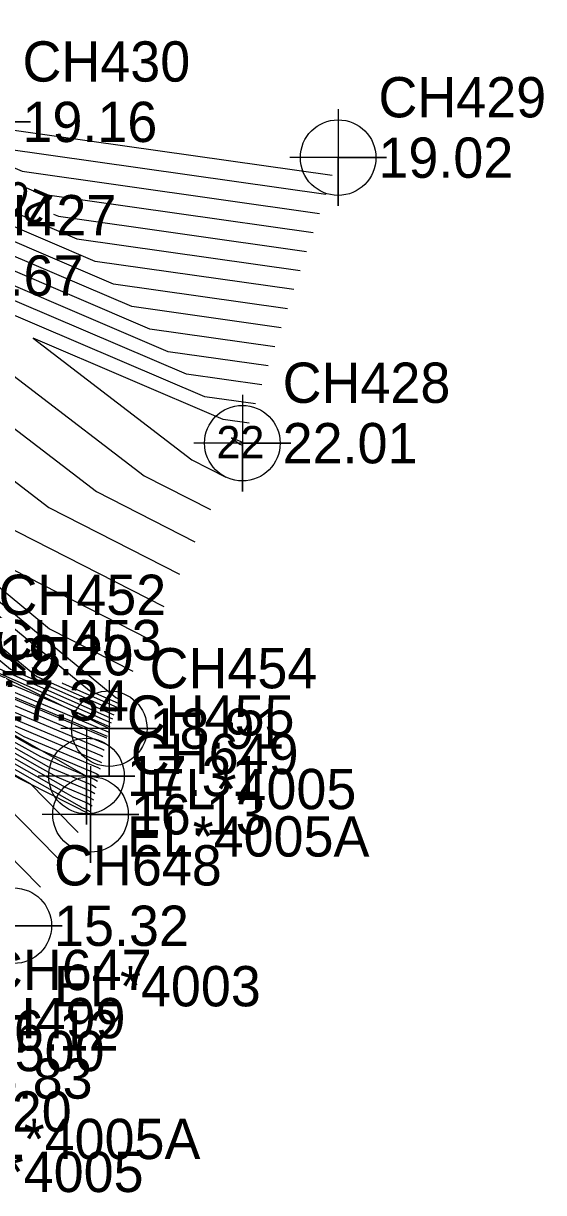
# Model space of a CAD drawing. Extents: x 2531902 to 2533249, y 715219 to 716099.
# Drawn here: x 2533024 to 2533056.3, y 715549.3 to 715621.9 of the extents above; entities that cross this region are included whole.
import ezdxf

# ---------------------------------------------------------------- set-up
doc = ezdxf.new("R2010")
doc.units = 0
for name, color, linetype in [('DTM Contours Major', 7, 'Continuous'), ('DTM Contours Major Text', 7, 'Continuous'), ('DTM Contours Minor', 7, 'Continuous'), ('Exist DTM Breakline', 7, 'Continuous'), ('Exist DTM Breakline Cogo Comment', 7, 'Continuous'), ('Exist DTM Breakline Cogo Elevation', 7, 'Continuous'), ('Exist DTM Breakline Cogo Number', 7, 'Continuous'), ('Exist DTM Breakline Cogo Point CELL', 7, 'Continuous'), ('Exist DTM Breakline Underwater', 7, 'Continuous'), ('Exist DTM Breakline Underwater Cogo Elevation', 7, 'Continuous'), ('Exist DTM Breakline Underwater Cogo Number', 7, 'Continuous'), ('Exist DTM Breakline Underwater Cogo Point CELL', 7, 'Continuous'), ('Exist DTM Drainline Cogo Comment', 7, 'Continuous'), ('Exist DTM Drainline Cogo Elevation', 7, 'Continuous'), ('Exist DTM Drainline Cogo Number', 7, 'Continuous'), ('Exist DTM Drainline Cogo Point CELL', 7, 'Continuous'), ('Exist DTM QL2 LIDAR Elevation Point', 7, 'Continuous'), ('Exist DTM Regular Point CELL', 7, 'Continuous'), ('Exist DTM Regular Point Cogo Elevation', 7, 'Continuous'), ('Exist DTM Regular Point Cogo Number', 7, 'Continuous'), ('Exist Hydro Stream or Body of Water', 7, 'Continuous'), ('Scratch_Level_2', 7, 'Continuous')]:
    doc.layers.add(name, color=color, linetype=linetype)

msp = doc.modelspace()

# ---------------------------------------------------------------- linework, layer by layer
at = {"layer": 'DTM Contours Major'}
for points in [[(2532946.87, 715617.429), (2532949.185, 715616.629), (2532951.913, 715615.738), (2532952.113, 715615.673), (2532964.207, 715610.955), (2532978.111, 715605.531), (2532979.345, 715604.806), (2532982.815, 715603.469), (2532989.141, 715601.029), (2532990.474, 715600.505), (2533006.727, 715590.482), (2533014.759, 715585.529), (2533016.174, 715584.657), (2533019.037, 715582.891), (2533020.493, 715582.065), (2533026.359, 715579.597), (2533029.394, 715578.257)], [(2533027.418, 715571.699), (2533027.176, 715571.946), (2533024.464, 715574.711), (2533004.98, 715585.771), (2533004.053, 715586.343), (2532998.79, 715589.588), (2532985.911, 715594.657), (2532977.232, 715595.627), (2532971.299, 715601.801), (2532961.938, 715607.296), (2532956.811, 715609.296), (2532955.068, 715609.865), (2532954.985, 715609.892), (2532953.857, 715610.261), (2532939.12, 715615.075)], [(2533025.904, 715610.066), (2533026.215, 715609.934), (2533041.601, 715607.751)], [(2533039.617, 715601.837), (2533031.881, 715602.934), (2533018.115, 715608.817), (2533015.15, 715607.045), (2533014.024, 715604.696)], [(2532980.883, 715601.698), (2532985.071, 715600.083), (2532987.721, 715599.04), (2532993.246, 715596.866), (2533011.19, 715585.8), (2533014.351, 715583.851), (2533020.078, 715580.601), (2533023.041, 715578.919), (2533028.859, 715576.471), (2533028.95, 715576.418)], [(2533014.217, 715601.218), (2533019.348, 715593.401), (2533022.641, 715590.878), (2533032.745, 715585.719)], [(2532977.433, 715600.777), (2532977.942, 715600.478), (2532978.745, 715600.007), (2532981.001, 715599.137), (2532981.993, 715598.747), (2532996.018, 715593.227), (2533007.622, 715586.072), (2533009.666, 715584.811), (2533024.201, 715576.56), (2533025.589, 715575.773), (2533028.313, 715574.627), (2533028.543, 715574.492)], [(2533037.633, 715595.922), (2533037.548, 715595.934), (2533036.934, 715596.197), (2533037.448, 715595.803), (2533037.558, 715595.747)], [(2533026.435, 715580.993), (2533026.495, 715580.944), (2533029.818, 715579.476)]]:
    msp.add_lwpolyline(points, dxfattribs=at)
at = {"layer": 'DTM Contours Minor'}
for points in [[(2532999.725, 715666.213), (2532993.26, 715656.52), (2532990, 715657.203), (2532984.051, 715655.949), (2532981.833, 715650), (2532981.031, 715641.031), (2532980.146, 715640.005), (2532980.058, 715630.034), (2532980.052, 715629.948), (2532982.278, 715610.95), (2532990.504, 715610.734), (2532998.305, 715604.477), (2533003.474, 715602.891), (2533010.173, 715601.89), (2533013.092, 715607.98), (2533019.576, 715611.855), (2533027.348, 715608.534), (2533041.204, 715606.568)], [(2532999.111, 715657.744), (2532992.201, 715647.385), (2532986.018, 715640.219), (2532985.959, 715633.551), (2532985.336, 715624.604), (2532986.72, 715612.801), (2532991.83, 715612.667), (2532996.677, 715608.78), (2533006.812, 715605.669), (2533010.47, 715605.123), (2533012.063, 715608.448), (2533020.306, 715613.374), (2533025.081, 715611.334), (2533041.997, 715608.934)], [(2532998.803, 715653.509), (2532993.605, 715645.716), (2532988.954, 715640.325), (2532988.909, 715635.309), (2532987.979, 715621.932), (2532988.94, 715613.726), (2532992.493, 715613.633), (2532995.863, 715610.931), (2533008.481, 715607.058), (2533010.618, 715606.739), (2533011.549, 715608.682), (2533020.671, 715614.134), (2533023.948, 715612.733), (2533042.394, 715610.117)], [(2532998.496, 715649.275), (2532995.01, 715644.048), (2532991.89, 715640.432), (2532991.86, 715637.067), (2532990.621, 715619.26), (2532991.161, 715614.652), (2532993.156, 715614.6), (2532995.049, 715613.082), (2533010.15, 715608.448), (2533010.766, 715608.356), (2533011.034, 715608.915), (2533021.036, 715614.893), (2533022.814, 715614.133), (2533042.791, 715611.3)], [(2532998.189, 715645.04), (2532996.414, 715642.379), (2532994.826, 715640.538), (2532994.81, 715638.826), (2532993.263, 715616.589), (2532993.382, 715615.578), (2532993.819, 715615.566), (2532994.235, 715615.233), (2532999.401, 715613.648), (2533018.93, 715614.175), (2533021.402, 715615.653), (2533021.681, 715615.533), (2533043.188, 715612.483)], [(2532960.276, 715619.792), (2532971.782, 715617.235), (2532979.897, 715609.186), (2532988.55, 715609.368), (2532989.991, 715608.846), (2532997.052, 715600.355), (2533004.549, 715595.73), (2533018.265, 715588.265), (2533019.992, 715587.199), (2533028.126, 715580.505), (2533029.903, 715579.72)], [(2532953.849, 715617.426), (2532972.271, 715610.766), (2532976.567, 715609.811), (2532979.597, 715606.806), (2532982.828, 715606.874), (2532989.957, 715604.29), (2532992.804, 715600.868), (2533011.106, 715589.575), (2533016.59, 715586.59), (2533019.985, 715584.495), (2533023.232, 715581.822), (2533029.648, 715578.988)], [(2532951.845, 715616.587), (2532976.27, 715607.757), (2532978.162, 715607.337), (2532979.497, 715606.013), (2532980.92, 715606.043), (2532989.946, 715602.772), (2532991.387, 715601.038), (2533013.292, 715587.523), (2533016.032, 715586.032), (2533019.983, 715583.593), (2533021.601, 715582.262), (2533029.564, 715578.745)], [(2532952.426, 715615.248), (2532971.074, 715607.973), (2532977.032, 715605.649), (2532979.285, 715604.326), (2532985.616, 715601.886), (2532988.327, 715600.84), (2532991.029, 715599.777), (2532997.994, 715595.482), (2533014.046, 715585.583), (2533016.873, 715583.84), (2533018.1, 715583.083), (2533021.003, 715581.435), (2533026.064, 715579.307), (2533029.296, 715577.947)], [(2532952.739, 715614.823), (2532975.954, 715605.766), (2532976.276, 715605.578), (2532979.225, 715603.846), (2532987.513, 715600.651), (2532991.158, 715599.216), (2532991.583, 715599.049), (2533013.332, 715585.638), (2533017.163, 715583.275), (2533017.603, 715583.025), (2533021.512, 715580.806), (2533029.187, 715577.578), (2533029.194, 715577.574)], [(2532953.053, 715614.397), (2532974.876, 715605.884), (2532976.484, 715604.94), (2532979.165, 715603.367), (2532986.699, 715600.462), (2532990.013, 715599.158), (2532992.138, 715598.321), (2533012.618, 715585.692), (2533016.226, 715583.467), (2533018.428, 715582.217), (2533022.022, 715580.177), (2533029.078, 715577.209), (2533029.113, 715577.189)], [(2532953.366, 715613.972), (2532973.798, 715606.002), (2532976.693, 715604.303), (2532979.105, 715602.887), (2532985.885, 715600.272), (2532988.867, 715599.099), (2532992.692, 715597.594), (2533011.904, 715585.746), (2533015.289, 715583.659), (2533019.253, 715581.409), (2533022.532, 715579.548), (2533028.969, 715576.84), (2533029.031, 715576.804)], [(2532957.341, 715613.936), (2532979.189, 715605.413), (2532979.405, 715605.286), (2532980.014, 715605.052), (2532988.789, 715601.668), (2532989.935, 715601.253), (2532989.971, 715601.209), (2533013.971, 715586.401), (2533015.46, 715585.483), (2533015.473, 715585.475), (2533015.475, 715585.473), (2533019.974, 715582.699), (2533019.984, 715582.694), (2533020.022, 715582.678), (2533029.479, 715578.501)], [(2532968.273, 715613.775), (2532974.972, 715612.286), (2532979.697, 715607.6), (2532984.735, 715607.706), (2532989.969, 715605.809), (2532994.22, 715600.697), (2533008.921, 715591.626), (2533017.148, 715587.149), (2533019.988, 715585.396), (2533024.864, 715581.383), (2533029.733, 715579.232)], [(2532953.992, 715613.122), (2532971.641, 715606.237), (2532977.109, 715603.028), (2532978.985, 715601.927), (2532984.257, 715599.894), (2532986.576, 715598.982), (2532993.801, 715596.138), (2533010.477, 715585.855), (2533013.414, 715584.043), (2533020.902, 715579.793), (2533023.551, 715578.289), (2533028.75, 715576.102), (2533028.869, 715576.033)], [(2532954.305, 715612.697), (2532970.563, 715606.355), (2532977.318, 715602.39), (2532978.925, 715601.447), (2532983.443, 715599.705), (2532985.43, 715598.923), (2532994.355, 715595.41), (2533009.763, 715585.909), (2533012.477, 715584.235), (2533021.727, 715578.985), (2533024.06, 715577.66), (2533028.641, 715575.734), (2533028.787, 715575.648)], [(2533040.807, 715605.386), (2533028.481, 715607.134), (2533019.21, 715611.096), (2533013.606, 715607.746), (2533010.025, 715600.274), (2533001.805, 715601.502), (2532999.12, 715602.326), (2532991.817, 715608.183), (2532998.468, 715600.185), (2533002.364, 715597.781), (2533018.823, 715588.823), (2533019.995, 715588.1), (2533029.757, 715580.065), (2533029.987, 715579.964)], [(2533040.41, 715604.203), (2533029.615, 715605.734), (2533018.845, 715610.336), (2533014.121, 715607.513), (2533010.922, 715600.838), (2533014.283, 715595.717), (2533000.893, 715600), (2533000.136, 715600.113), (2532999.934, 715600.175), (2532999.384, 715600.616), (2532999.885, 715600.014), (2533000.178, 715599.833), (2533019.381, 715589.381), (2533019.997, 715589.001), (2533025.656, 715584.344), (2533030.819, 715581.707)], [(2533040.013, 715603.02), (2533030.748, 715604.334), (2533018.48, 715609.577), (2533014.635, 715607.279), (2533012.032, 715601.847), (2533019.442, 715590.558), (2533017.892, 715591.054), (2533019.94, 715589.94), (2533020, 715589.902), (2533020.552, 715589.448), (2533031.782, 715583.713)], [(2533039.22, 715600.654), (2533033.015, 715601.534), (2533017.75, 715608.058), (2533015.664, 715606.811), (2533014.252, 715603.865), (2533018.617, 715597.215), (2533025.602, 715591.863), (2533033.707, 715587.724)], [(2533028.218, 715572.951), (2533027.876, 715573.151), (2533027.627, 715573.256), (2533027.5, 715573.328), (2533005.917, 715585.579), (2533004.767, 715586.289), (2532998.236, 715590.316), (2532982.253, 715596.606), (2532977.896, 715597.093), (2532974.918, 715600.193), (2532963.016, 715607.178)], [(2533028.299, 715573.337), (2533027.985, 715573.52), (2533027.118, 715573.885), (2533026.676, 715574.136), (2533006.854, 715585.387), (2533005.48, 715586.234), (2532997.682, 715591.043), (2532978.595, 715598.556), (2532978.56, 715598.559), (2532978.537, 715598.584), (2532964.094, 715607.06)], [(2533038.823, 715599.471), (2533034.148, 715600.134), (2533017.384, 715607.298), (2533016.178, 715606.577), (2533015.362, 715604.874), (2533017.886, 715601.028), (2533028.564, 715592.848), (2533034.67, 715589.73)], [(2532965.172, 715606.943), (2532978.359, 715599.203), (2532978.625, 715599.047), (2532979.373, 715598.759), (2532979.702, 715598.629), (2532997.127, 715591.771), (2533006.194, 715586.18), (2533007.791, 715585.195), (2533025.851, 715574.944), (2533026.608, 715574.514), (2533028.095, 715573.889), (2533028.381, 715573.722)], [(2532966.251, 715606.825), (2532978.151, 715599.841), (2532978.685, 715599.527), (2532980.187, 715598.948), (2532980.848, 715598.688), (2532996.573, 715592.499), (2533006.908, 715586.126), (2533008.728, 715585.003), (2533025.026, 715575.752), (2533026.099, 715575.143), (2533028.204, 715574.258), (2533028.462, 715574.107)], [(2532968.407, 715606.59), (2532977.734, 715601.116), (2532978.805, 715600.487), (2532981.815, 715599.326), (2532983.139, 715598.805), (2532995.464, 715593.955), (2533008.335, 715586.017), (2533010.603, 715584.619), (2533023.377, 715577.368), (2533025.079, 715576.402), (2533028.422, 715574.996), (2533028.625, 715574.878)], [(2532969.485, 715606.472), (2532977.526, 715601.753), (2532978.865, 715600.967), (2532982.629, 715599.516), (2532984.285, 715598.864), (2532994.91, 715594.682), (2533009.049, 715585.963), (2533011.54, 715584.427), (2533022.552, 715578.176), (2533024.57, 715577.031), (2533028.532, 715575.365), (2533028.706, 715575.263)], [(2533038.426, 715598.288), (2533035.282, 715598.734), (2533017.019, 715606.539), (2533016.693, 715606.344), (2533016.472, 715605.883), (2533017.155, 715604.842), (2533031.525, 715593.833), (2533035.633, 715591.736)], [(2533025.081, 715568.308), (2533024.981, 715568.41), (2533013.199, 715580.426), (2533003.105, 715586.155), (2533002.625, 715586.451), (2532999.899, 715588.132), (2532993.228, 715590.758), (2532975.904, 715592.695), (2532964.062, 715605.019)], [(2533026.25, 715570.004), (2533026.079, 715570.178), (2533018.831, 715577.569), (2533004.043, 715585.963), (2533003.339, 715586.397), (2532999.345, 715588.86), (2532989.57, 715592.707), (2532976.568, 715594.161), (2532967.681, 715603.41)], [(2533038.029, 715597.105), (2533036.415, 715597.334), (2533024.625, 715602.373), (2533034.486, 715594.818), (2533036.595, 715593.741)]]:
    msp.add_lwpolyline(points, dxfattribs=at)
at = {"layer": 'Exist DTM Breakline'}
msp.add_lwpolyline([(2532892.328, 715646.649), (2532892.824, 715644.229), (2532893.495, 715643.959), (2532907.123, 715635.526), (2532917.688, 715630.637), (2532930.112, 715624.224), (2532951.535, 715616.457), (2532989.934, 715601.214), (2533019.98, 715582.698), (2533029.354, 715578.142)], dxfattribs=at)
at = {"layer": 'Exist DTM Breakline Cogo Point CELL'}
for points in [[(2533029.354, 715581.142), (2533029.354, 715575.142), (2533029.354, 715578.142), (2533032.354, 715578.142), (2533026.354, 715578.142)], [(2533027.94, 715578.202), (2533027.94, 715572.202), (2533027.94, 715575.202), (2533030.94, 715575.202), (2533024.94, 715575.202)]]:
    msp.add_lwpolyline(points, dxfattribs=at)
for centre in [(2533029.354, 715578.142), (2533027.94, 715575.202)]:
    msp.add_circle(centre, 2.344, dxfattribs=at)
at = {"layer": 'Exist DTM Breakline Underwater'}
msp.add_lwpolyline([(2532646.748, 715755.182), (2532668.676, 715717.147), (2532677.241, 715702.567), (2532689.842, 715666.582), (2532701.723, 715652.924), (2532713.134, 715647.155), (2532737.59, 715643.253), (2532756.176, 715636.457), (2532783.406, 715639.452), (2532803.254, 715642.171), (2532813.801, 715644.931), (2532836.277, 715651.081), (2532865.559, 715653.815), (2532885.826, 715645.124), (2532889.946, 715643.683), (2532906.865, 715630.423), (2532927.34, 715618.228), (2532957.965, 715607.729), (2532978.566, 715598.571), (2533001.091, 715586.568), (2533028.19, 715572.821)], dxfattribs=at)
at = {"layer": 'Exist DTM Breakline Underwater Cogo Point CELL'}
msp.add_lwpolyline([(2533028.19, 715575.821), (2533028.19, 715569.821), (2533028.19, 715572.821), (2533031.19, 715572.821), (2533025.19, 715572.821)], dxfattribs=at)
msp.add_circle((2533028.19, 715572.821), 2.344, dxfattribs=at)
at = {"layer": 'Exist DTM Drainline Cogo Point CELL'}
msp.add_lwpolyline([(2533023.429, 715568.909), (2533023.429, 715562.909), (2533023.429, 715565.909), (2533026.429, 715565.909), (2533020.429, 715565.909)], dxfattribs=at)
msp.add_circle((2533023.429, 715565.909), 2.344, dxfattribs=at)
at = {"layer": 'Exist DTM QL2 LIDAR Elevation Point'}
msp.add_line((2533030, 715580), (2533030, 715580), dxfattribs=at)
at = {"layer": 'Exist DTM Regular Point CELL'}
for points in [[(2533021.47, 715618.794), (2533021.47, 715612.794), (2533021.47, 715615.794), (2533024.47, 715615.794), (2533018.47, 715615.794)], [(2533043.554, 715616.575), (2533043.554, 715610.575), (2533043.554, 715613.575), (2533046.554, 715613.575), (2533040.554, 715613.575)], [(2533037.611, 715598.857), (2533037.611, 715592.857), (2533037.611, 715595.857), (2533040.611, 715595.857), (2533034.611, 715595.857)]]:
    msp.add_lwpolyline(points, dxfattribs=at)
for centre in [(2533043.554, 715613.575), (2533037.611, 715595.857)]:
    msp.add_circle(centre, 2.344, dxfattribs=at)
at = {"layer": 'Exist Hydro Stream or Body of Water'}
msp.add_lwpolyline([(2532952.661, 715614.929), (2532976.224, 715605.737), (2532979.24, 715603.966), (2532987.717, 715600.698), (2532991.445, 715599.231), (2533013.51, 715585.624), (2533017.397, 715583.227), (2533021.385, 715580.964), (2533029.215, 715577.67)], dxfattribs=at)
at = {"layer": 'Scratch_Level_2'}
msp.add_lwpolyline([(2532888.673, 715646.27), (2532890.953, 715646.451), (2532891.078, 715645.138), (2532893.279, 715642.616), (2532904.807, 715634.438), (2532916.512, 715629.517), (2532928.719, 715621.672), (2532951.454, 715614.479), (2532989.004, 715600.335), (2533019.7, 715579.89), (2533027.94, 715575.202)], dxfattribs=at)

# ---------------------------------------------------------------- texts
at = {"layer": 'DTM Contours Major Text'}
for rotation, p in [(156.86069, (2533025.957, 715611.131)), (320.54571, (2533022.997, 715582.527))]:
    msp.add_text('20', height=2, rotation=rotation, dxfattribs=at).set_placement(p)
msp.add_text('22', height=2, dxfattribs=at).set_placement((2533036.003, 715594.922))
at = {"layer": 'Exist DTM Breakline Cogo Comment'}
for s, p in [('EL*4005', (2533031.854, 715573.142)), ('EL*4005A', (2533030.44, 715570.202)), ('EL*4005A', (2533019.954, 715551.427)), ('EL*4005', (2533018.656, 715549.384))]:
    msp.add_text(s, height=2.5, dxfattribs=at).set_placement(p)
at = {"layer": 'Exist DTM Breakline Cogo Elevation'}
for s, p in [('19.20', (2533022.48, 715581.448)), ('17.34', (2533022.2, 715578.64)), ('18.91', (2533031.854, 715576.892)), ('17.31', (2533030.44, 715573.952)), ('16.83', (2533019.954, 715555.177)), ('19.20', (2533018.656, 715553.134))]:
    msp.add_text(s, height=2.5, dxfattribs=at).set_placement(p)
at = {"layer": 'Exist DTM Breakline Cogo Number'}
for s, p in [('CH452', (2533022.48, 715585.198)), ('CH453', (2533022.2, 715582.39)), ('CH454', (2533031.854, 715580.642)), ('CH455', (2533030.44, 715577.702)), ('CH499', (2533019.954, 715558.927)), ('CH500', (2533018.656, 715556.884))]:
    msp.add_text(s, height=2.5, dxfattribs=at).set_placement(p)
at = {"layer": 'Exist DTM Breakline Underwater Cogo Elevation'}
for s, p in [('16.13', (2533030.69, 715571.571)), ('16.12', (2533021.577, 715558.165))]:
    msp.add_text(s, height=2.5, dxfattribs=at).set_placement(p)
at = {"layer": 'Exist DTM Breakline Underwater Cogo Number'}
for s, p in [('CH649', (2533030.69, 715575.321)), ('CH647', (2533021.577, 715561.915))]:
    msp.add_text(s, height=2.5, dxfattribs=at).set_placement(p)
at = {"layer": 'Exist DTM Drainline Cogo Comment'}
msp.add_text('EL*4003', height=2.5, dxfattribs=at).set_placement((2533025.929, 715560.909))
at = {"layer": 'Exist DTM Drainline Cogo Elevation'}
msp.add_text('15.32', height=2.5, dxfattribs=at).set_placement((2533025.929, 715564.659))
at = {"layer": 'Exist DTM Drainline Cogo Number'}
msp.add_text('CH648', height=2.5, dxfattribs=at).set_placement((2533025.929, 715568.409))
at = {"layer": 'Exist DTM Regular Point Cogo Elevation'}
for s, p in [('19.16', (2533023.97, 715614.544)), ('19.02', (2533046.054, 715612.325)), ('21.67', (2533019.384, 715605.007)), ('22.01', (2533040.111, 715594.607))]:
    msp.add_text(s, height=2.5, dxfattribs=at).set_placement(p)
at = {"layer": 'Exist DTM Regular Point Cogo Number'}
for s, p in [('CH430', (2533023.97, 715618.294)), ('CH429', (2533046.054, 715616.075)), ('CH427', (2533019.384, 715608.757)), ('CH428', (2533040.111, 715598.357))]:
    msp.add_text(s, height=2.5, dxfattribs=at).set_placement(p)

doc.saveas('drawing.dxf')
